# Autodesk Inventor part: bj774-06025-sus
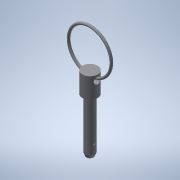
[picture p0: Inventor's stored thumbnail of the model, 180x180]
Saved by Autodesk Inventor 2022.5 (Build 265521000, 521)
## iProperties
Created: 2016-12
Part Number: bj774-06025-sus
Material: 一般
Document SubType Name: Modeling
Designer: imaocorp
Density: 1 g/cm^3
Appearance: 既定
Author: imaocorp
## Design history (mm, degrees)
node "bj774-06025-sus.x_t1"
node "bj774-06025-sus"
node "Base1"
